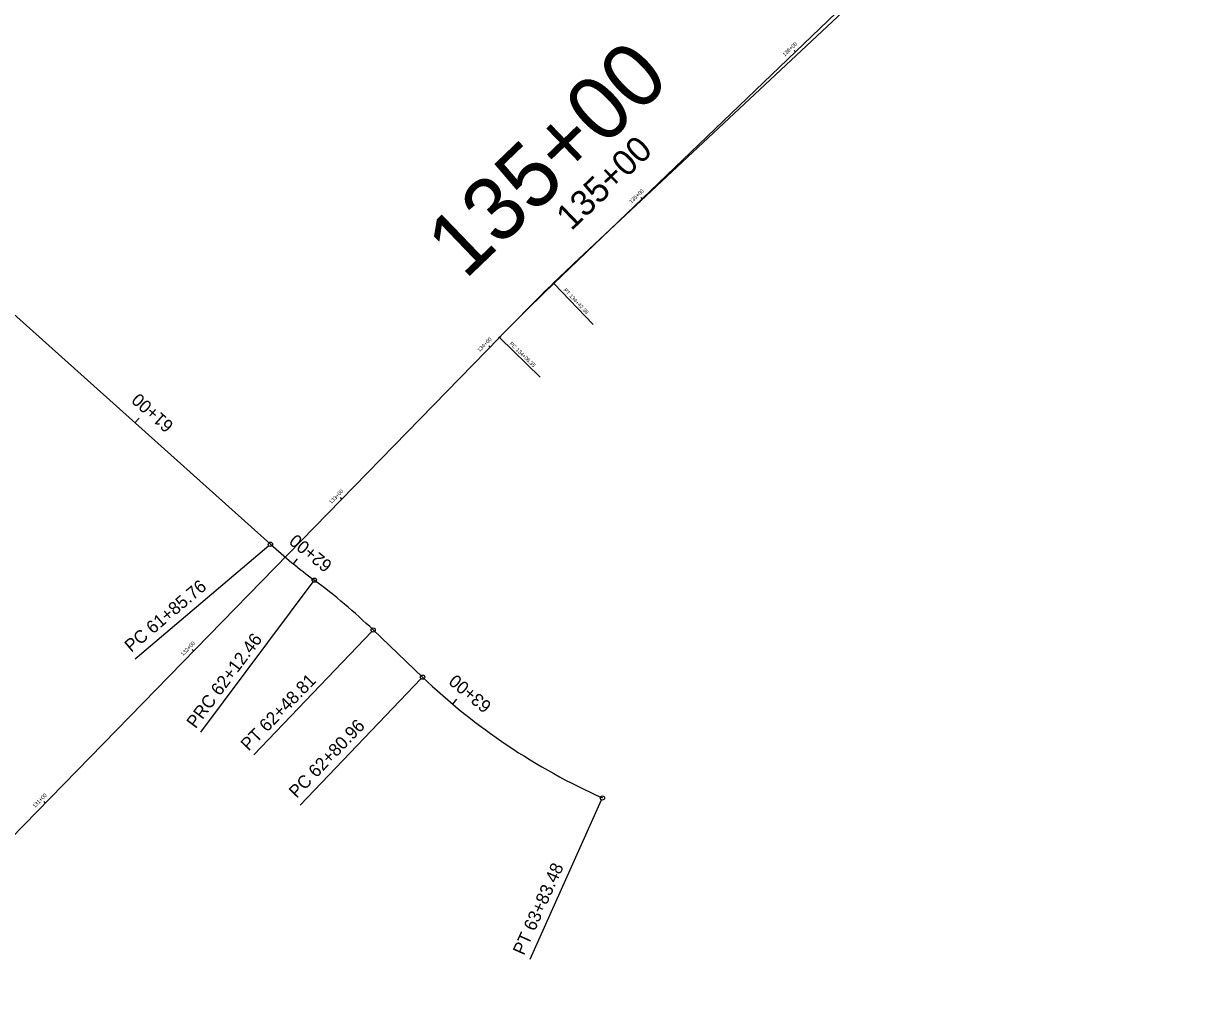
# Model space of a CAD drawing. Extents: x 2252491 to 2257126, y 13788370 to 13792743.
# Drawn here: x 2254813 to 2255367, y 13790613 to 13791067 of the extents above; entities that cross this region are included whole.
import ezdxf

# ---------------------------------------------------------------- set-up
doc = ezdxf.new("R2010")
doc.units = 0
for name, color, linetype in [('D_ALIGN_1', 7, 'Continuous'), ('D_ALIGN_ANNO_1', 7, 'Continuous'), ('D_ALIGN_ANNO_200_drn', 7, 'Continuous'), ('D_ALIGN_ANNO_DRN_300', 7, 'Continuous'), ('D_ALIGN_ANNO_RR_STOEGER', 7, 'Continuous'), ('D_ALIGN_RR_STOEGER', 7, 'Continuous'), ('Default', 7, 'Continuous')]:
    doc.layers.add(name, color=color, linetype=linetype)

msp = doc.modelspace()

# ---------------------------------------------------------------- linework, layer by layer
at = {"layer": 'D_ALIGN_1'}
for p, q in [((2255062.92, 13790944.99), (2255367.32, 13791237.32)), ((2254268.72, 13790131.48), (2255037.34, 13790919.6))]:
    msp.add_line(p, q, dxfattribs=at)
msp.add_arc((2255824.84, 13790151.59), 1100, 133.84074, 135.71793, dxfattribs=at)
at = {"layer": 'D_ALIGN_ANNO_1'}
for p, q in [((2255176.6, 13791054.16), (2255175.98, 13791054.81)), ((2255104.47, 13790984.9), (2255103.85, 13790985.54)), ((2255063.13, 13790944.77), (2255081.46, 13790925.68)), ((2255037.55, 13790919.39), (2255056.5, 13790900.92)), ((2255032.91, 13790915.06), (2255032.26, 13790915.69)), ((2254963.09, 13790843.47), (2254962.44, 13790844.1)), ((2254893.27, 13790771.88), (2254892.62, 13790772.51)), ((2254823.45, 13790700.29), (2254822.81, 13790700.92))]:
    msp.add_line(p, q, dxfattribs=at)
for centre in [(2255062.92, 13790944.99), (2255037.34, 13790919.6)]:
    msp.add_circle(centre, 0.3, dxfattribs=at)
at = {"layer": 'D_ALIGN_ANNO_RR_STOEGER'}
for p, q in [((2254865.61, 13790879.39), (2254867.61, 13790881.62)), ((2254865.82, 13790768.25), (2254928.71, 13790821.51)), ((2254940.3, 13790812.91), (2254942.2, 13790815.23)), ((2254896.64, 13790733.66), (2254949.52, 13790804.44)), ((2254977.17, 13790781.05), (2254921.64, 13790722.97)), ((2254943.46, 13790699.27), (2255000.4, 13790758.84)), ((2255015.27, 13790746.85), (2255017.2, 13790749.14)), ((2255051.72, 13790626.64), (2255085.35, 13790701.72))]:
    msp.add_line(p, q, dxfattribs=at)
for centre in [(2254929.47, 13790822.15), (2254950.12, 13790805.25), (2254977.86, 13790781.77), (2255001.09, 13790759.56), (2255085.76, 13790702.63)]:
    msp.add_circle(centre, 1, dxfattribs=at)
at = {"layer": 'D_ALIGN_RR_STOEGER'}
for p, q in [((2254791.14, 13790946.13), (2254929.47, 13790822.15)), ((2254977.86, 13790781.77), (2255001.09, 13790759.56))]:
    msp.add_line(p, q, dxfattribs=at)
for centre, start, end in [((2255129.69, 13791045.57), 228.135, 233.2336), ((2254770.56, 13790564.92), 46.2898, 53.2334), ((2255208.4, 13790976.42), 226.2898, 245.8708)]:
    msp.add_arc(centre, 300, start, end, dxfattribs=at)
at = {"layer": 'Default'}
msp.add_line((2255072.31, 13790954.36), (2255257.38, 13791127.71), dxfattribs=at)
msp.add_arc((2255585.02, 13790406.98), 750, 133.12633, 135.71793, dxfattribs=at)

# ---------------------------------------------------------------- texts
at = {"layer": 'D_ALIGN_ANNO_1'}
for s, rotation, p in [('136+00', 43.8407, (2255171.6, 13791051.85)), ('135+00', 43.8407, (2255099.47, 13790982.59)), ('PT 134+42.38', 313.8407, (2255067.31, 13790941.72)), ('134+00', 45.7179, (2255027.98, 13790912.59)), ('PC 134+06.35', 315.7179, (2255041.83, 13790916.48)), ('133+00', 45.7179, (2254958.16, 13790841)), ('132+00', 45.7179, (2254888.34, 13790769.41)), ('131+00', 45.7179, (2254818.53, 13790697.82))]:
    msp.add_text(s, height=1.8, rotation=rotation, dxfattribs=at).set_placement(p)
at = {"layer": 'D_ALIGN_ANNO_200_drn'}
msp.add_text('135+00', height=12, rotation=43.8407, dxfattribs=at).set_placement((2255071.12, 13790969.5))
at = {"layer": 'D_ALIGN_ANNO_DRN_300'}
msp.add_text('135+00', height=30, rotation=43.8407, dxfattribs=at).set_placement((2255021.1, 13790946.42))
at = {"layer": 'D_ALIGN_ANNO_RR_STOEGER'}
for s, rotation, p in [('61+00', 138.135, (2254884.33, 13790878.73)), ('62+00', 140.8548, (2254959.03, 13790813.13)), ('PC 61+85.76', 40.2592, (2254863.95, 13790770.96)), ('PRC 62+12.46', 53.2336, (2254894.25, 13790734.99)), ('PT 62+48.81', 45.6588, (2254919.14, 13790724.47)), ('63+00', 139.927, (2255034, 13790746.77)), ('PC 62+80.96', 46.2898, (2254941.84, 13790702.18)), ('PT 63+83.48', 65.8708, (2255048.79, 13790628.17))]:
    msp.add_text(s, height=6, rotation=rotation, dxfattribs=at).set_placement(p)

doc.saveas('drawing.dxf')
